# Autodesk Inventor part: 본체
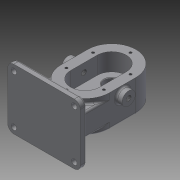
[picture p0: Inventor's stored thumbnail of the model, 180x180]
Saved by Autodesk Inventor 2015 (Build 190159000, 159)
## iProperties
Created: 2020-09
Part Number: 본체
Material: 일반
Document SubType Name: Modeling
Designer: Administrator
Density: 1 g/cm^3
Appearance: 기본값
Author: Administrator
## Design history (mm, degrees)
sketch "스케치1"
  geometry: L1 (0, 0)-(0, -44); L2 (-40, 0)-(-40, -44); L3 (40, -44)-(40, 0); A1 r 40 centre (0, 0) between (40, 0) and (-40, 0); A2 r 40 centre (0, -44) between (-40, -44) and (40, -44); 1 further point
  constraints: 8 end point, 4 point on circle, 4 tangent, 2 centre point, 1 midpoint, 1 parallel, 1 vertical
  dimensions: "d0" = 44 distance of L1.start L1.end; "d1" = 80 diameter of A2
extrude "돌출1" new body sketch "스케치1" distance "d2" = 53; taper "d3" = 0 deg
sketch "스케치2"
  geometry: L1 (0, 0)-(0, -44); L2 (-24, 0)-(-24, -44); L3 (24, -44)-(24, 0); A1 r 24 centre (0, 0) between (24, 0) and (-24, 0); A2 r 24 centre (0, -44) between (-24, -44) and (24, -44); 1 further point
  constraints: 8 end point, 4 point on circle, 4 tangent, 2 centre point, 1 midpoint, 1 parallel, 1 vertical
  dimensions: "d4" = 44 distance of L1.start L1.end; "d5" = 48 diameter of A2
extrude "돌출2" cut sketch "스케치2" distance "d6" = 29; taper "d7" = 0 deg
sketch "스케치3"
  geometry: L1 (-24, -44)-(-24, 0) reference; L2 (24, 0)-(24, -44) reference; C1 r 12.5 at (0, 0); C2 r 12.5 at (0, -44); A1 r 24 centre (0, -44) between (-24, -44) and (24, -44) reference; A2 r 24 centre (0, 0) between (24, 0) and (-24, 0) reference; 1 further point
  constraints: 2 centre point, 2 coincident
  dimensions: "d8" = 25 diameter of C1; "d9" = 25 diameter of C2
extrude "돌출3" cut sketch "스케치3" distance "d10" = 15; taper "d11" = 0 deg
sketch "스케치4"
  geometry: L1 (40, 0)-(40, -44) reference; L2 (-40, -44)-(-40, 0) reference; C1 r 19 at (0, 0); A1 r 40 centre (0, 0) between (40, 0) and (-40, 0) reference; A2 r 40 centre (0, -44) between (-40, -44) and (40, -44) reference; 1 further point
  constraints: 1 centre point, 1 coincident
  dimensions: "d12" = 38 diameter of C1
extrude "돌출4" join sketch "스케치4" distance "d13" = 17; taper "d14" = 0 deg
sketch "스케치5"
  geometry: C1 r 19 at (0, 0) reference; C2 r 14 at (0, 0); 1 further point
  constraints: 1 centre point, 1 coincident
  dimensions: "d15" = 28 diameter of C2
extrude "돌출5" cut sketch "스케치5" distance "d16" = 7.3; taper "d17" = 0 deg
sketch "스케치6"
  geometry: C1 r 14 at (0, 0) reference; C2 r 8.5 at (0, 0); 1 further point
  constraints: 1 centre point, 1 coincident
  dimensions: "d18" = 17 diameter of C2
extrude "돌출6" cut sketch "스케치6" stored distance "d19" = 7.3; taper "d20" = 0 deg
chamfer "모따기1" distance "d21" = 0.7; stored, may be unused: second distance "d22" = 2, angle "d23" = 30 deg
chamfer "모따기2" distance "d24" = 1; stored, may be unused: second distance "d25" = 2, angle "d26" = 30 deg
sketch "스케치7"
  geometry: L1 (-24, -44)-(-24, 0) reference; L2 (24, 0)-(24, -44) reference; L3 (-40, 0)-(-40, -44) reference; L4 (40, -44)-(40, 0) reference; A1 r 24 centre (0, -44) between (-24, -44) and (24, -44) reference; A2 r 24 centre (0, 0) between (24, 0) and (-24, 0) reference; A3 r 40 centre (0, -44) between (-40, -44) and (40, -44) reference; A4 r 40 centre (0, 0) between (40, 0) and (-40, 0) reference; A5 r 31 centre (0, 0) between (31, 0) and (0, 31); A6 r 31 centre (0, -44) between (-31, -44) and (31, -44); 3 further points
  constraints: 6 point on circle, 2 centre point, 2 coincident
  dimensions: "d28" = 62 diameter of A5; "d29" = 62 diameter of A6; "d30" = 9 distance from line of A5.start L4; "d31" = 9 distance from line of A6.end L4; "d32" = 40 distance from line of A5.end L4; "d33" = 40 distance from line of point (0, -75) L4; "d34" = 71 distance from line of point (-31, 0) L4; "d35" = 71 distance from line of A6.start L4
hole "구멍1" sketch "스케치7" at (31, 0), (0, 31), (-31, 0), (-31, -44), (31, -44), (0, -75) diameter "d36" = 4.134; stored, may be unused: countersink angle "d40" = 90 deg, drill point angle "d42" = 118 deg; dims "d37" = 10, "d38" = 4, "d39" = 2, "d41" = 12
sketch "스케치8"
  geometry: L1 (-53, 0)-(-53, 44) reference; L2 (-53, 22)-(-39, 22); C1 r 11 at (-39, 22); 1 further point
  constraints: 2 end point, 1 centre point, 1 coincident, 1 horizontal, 1 midpoint
  dimensions: "d43" = 14 distance of L2.start L2.end; "d44" = 22 diameter of C1
extrude "돌출7" join sketch "스케치8" distance "d45" = 10; taper "d46" = 0 deg
sketch "스케치9"
  geometry: L1 (53, 44)-(53, 0) reference; L2 (53, 22)-(39, 22); C1 r 11 at (39, 22); 1 further point
  constraints: 2 end point, 1 centre point, 1 coincident, 1 horizontal, 1 midpoint
  dimensions: "d47" = 14 distance of L2.start L2.end; "d48" = 22 diameter of C1
extrude "돌출8" join sketch "스케치9" distance "d49" = 10; taper "d50" = 0 deg
sketch "스케치10"
  geometry: C1 r 11 at (0, 0) reference; 2 further points
  constraints: 1 coincident
hole "구멍2" sketch "스케치10" at (0, 0) diameter "d51" = 8.376; stored, may be unused: countersink angle "d55" = 90 deg, drill point angle "d57" = 0 deg; dims "d52" = 30, "d53" = 4, "d54" = 2, "d56" = 40
sketch "스케치11"
  geometry: C1 r 11 at (0, 0) reference; 2 further points
  constraints: 1 coincident
hole "구멍3" sketch "스케치11" at (0, 0) diameter "d58" = 8.376; stored, may be unused: countersink angle "d62" = 90 deg, drill point angle "d64" = 0 deg; dims "d59" = 30, "d60" = 4, "d61" = 2, "d63" = 40
node "작업 평면1"
sketch "스케치12"
  geometry: L1 (-19, -17)-(19, -17) reference; L2 (0, -17)-(60, -17); L3 (60, -17)-(60, 83); L4 (60, 83)-(-60, 83); L5 (-60, 83)-(-60, -17); L6 (-60, -17)-(0, -17); 1 further point
  constraints: 10 end point, 3 perpendicular, 1 collinear, 1 horizontal, 1 midpoint, 1 point on line
  dimensions: "d66" = 60 distance of L2.start L2.end; "d67" = 100 distance of L2.end L3.end; "d68" = 120 distance of L3.end L4.end
extrude "돌출9" join sketch "스케치12" distance "d69" = 10; taper "d70" = 0 deg
node "작업 평면2"
sketch "스케치13"
  geometry: L1 (84, 68)-(84, 112) reference; L2 (36, 112)-(36, 68) reference; L3 (100, 112)-(100, 68) reference; L4 (20, 68)-(20, 112) reference; L5 (20, 68)-(20, 10); L6 (0, 10)-(120, 10) reference; L7 (20, 68)-(20, 112) reference; L8 (100, 68)-(100, 10); L9 (100, 10)-(20, 10); C1 r 2.067 at (29, 68) reference; C2 r 2.067 at (91, 112) reference; C3 r 2.067 at (29, 112) reference; C4 r 2.067 at (60, 143) reference; C5 r 2.067 at (91, 68) reference; C6 r 2.067 at (60, 37) reference; A1 r 24 centre (60, 68) between (36, 68) and (84, 68) reference; A2 r 24 centre (60, 112) between (84, 112) and (36, 112) reference; A3 r 40 centre (60, 68) between (20, 68) and (100, 68) reference; A4 r 40 centre (60, 112) between (100, 112) and (20, 112) reference; A5 r 40 centre (60, 68) between (20, 68) and (100, 68) reference; A6 r 40.121 centre (60, 71.116) between (20, 68) and (100, 68); 1 further point
  constraints: 6 end point, 2 collinear, 2 point on circle, 2 point on line, 1 centre point, 1 perpendicular, 1 tangent
  dimensions: "d72" = 40.12121 radius of A6
extrude "돌출10" join sketch "스케치13" distance "d73" = 37; taper "d74" = 0 deg
sketch "스케치14"
  geometry: L1 (-60, 17)-(-60, -83) reference; L2 (-60, -83)-(60, -83) reference; 2 further points
  constraints: 1 other
  dimensions: "d75" = 60 distance from line of L1 point (0, -71); "d76" = 12 distance from line of L2 point (0, -71)
feature "엠보싱1" sketch "스케치14" dims "d0" = 44, "d1" = 80, "d77" = 0.5, "d78" = 0
fillet "모깎기2" dims "d79" = 3
fillet "모깎기3" dims "d80" = 3
fillet "모깎기4" dims "d81" = 3
fillet "모깎기5" dims "d82" = 3
fillet "모깎기6" dims "d83" = 3
fillet "모깎기7" dims "d84" = 0.5
fillet "모깎기8" dims "d85" = 3
fillet "모깎기9" dims "d86" = 3
fillet "모깎기10" dims "d87" = 10
fillet "모깎기11" dims "d88" = 3
sketch "스케치15"
  geometry: A1 r 7 centre (50, -73) between (50, -80) and (57, -73) reference; A2 r 7 centre (50, 7) between (57, 7) and (50, 14) reference; A3 r 7 centre (-50, 7) between (-50, 14) and (-57, 7) reference; A4 r 7 centre (-50, -73) between (-57, -73) and (-50, -80) reference; 5 further points
  constraints: 4 coincident
hole "구멍4" sketch "스케치15" at (50, 7), (-50, 7), (-50, -73), (50, -73) diameter "d89" = 9; stored, may be unused: countersink angle "d93" = 90 deg, drill point angle "d95" = 0 deg; dims "d90" = 6, "d91" = 4, "d92" = 2, "d94" = 11
node "솔리드1"
node "투영된 루프1"
node "투영된 루프2"
node "투영된 루프3"
node "투영된 루프4"
node "투영된 루프5"
node "투영된 루프6"
node "투영된 루프7"
other parameters: "d65" = -112, "d71" = -62
